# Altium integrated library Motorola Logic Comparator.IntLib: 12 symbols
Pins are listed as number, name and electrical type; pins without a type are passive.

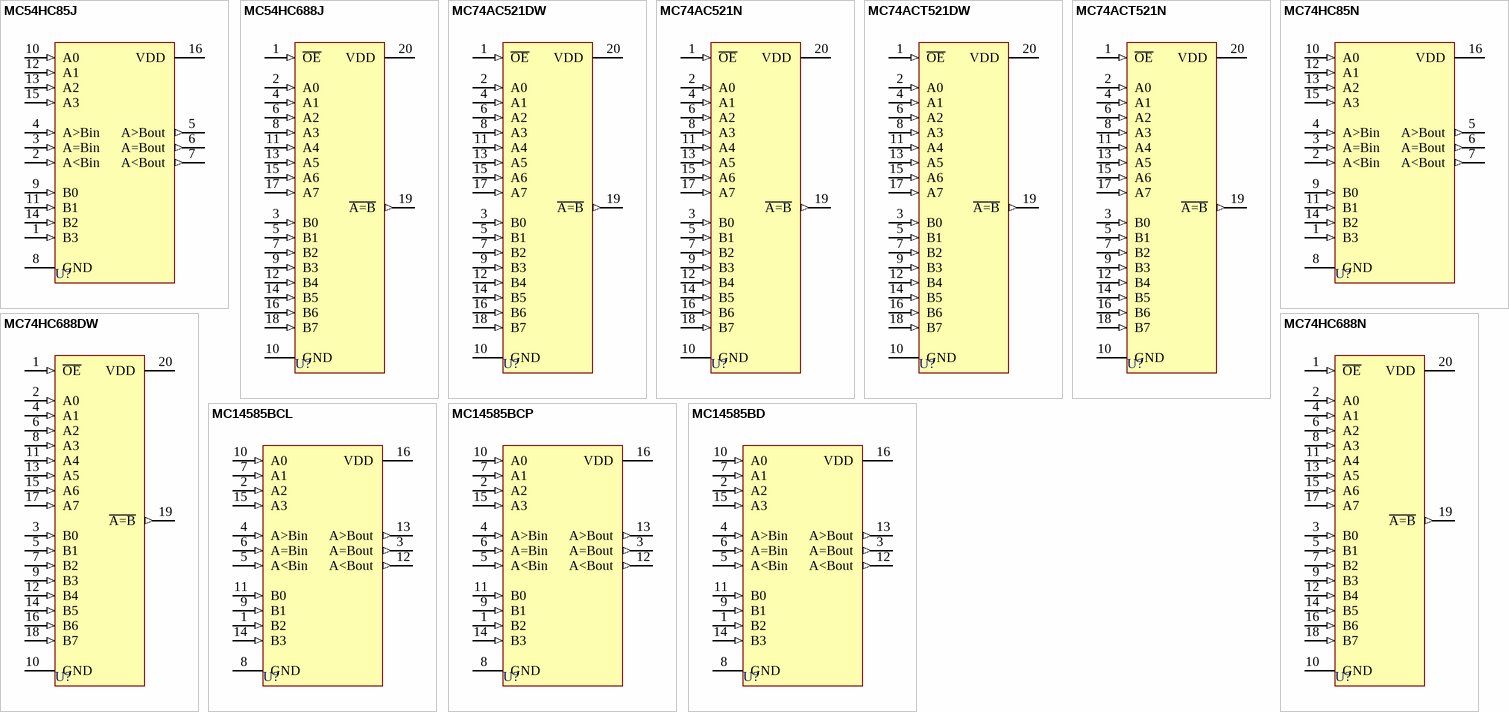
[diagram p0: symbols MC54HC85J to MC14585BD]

## MC54HC85J
designator U?
4-Bit Magnitude Comparator
footprint 620-09 (DIP; 16 Leads; Row Spacing 7.62 mm; Pitch 2.54 mm)
3D model 620-09 (DIP; 16 Leads; Row Spacing 7.62 mm; Pitch 2.54 mm)
signal-integrity model MC54HC85J
pins: 1 B3 (in), 2 A<Bin (in), 3 A=Bin (in), 4 A>Bin (in), 5 A>Bout (out), 6 A=Bout (out), 7 A<Bout (out), 8 GND (power), 9 B0 (in), 10 A0 (in), 11 B1 (in), 12 A1 (in), 13 A2 (in), 14 B2 (in), 15 A3 (in), 16 VDD (power)

## MC54HC688J
designator U?
8-Bit Equality Comparator
footprint 732-03 (DIP; 20 Leads; Row Spacing 7.62 mm; Pitch 2.54 mm)
3D model 732-03 (DIP; 20 Leads; Row Spacing 7.62 mm; Pitch 2.54 mm)
signal-integrity model MC54HC688J
pins: 1 ~{OE} (in), 2 A0 (in), 3 B0 (in), 4 A1 (in), 5 B1 (in), 6 A2 (in), 7 B2 (in), 8 A3 (in), 9 B3 (in), 10 GND (power), 11 A4 (in), 12 B4 (in), 13 A5 (in), 14 B5 (in), 15 A6 (in), 16 B6 (in), 17 A7 (in), 18 B7 (in), 19 ~{A=B} (out), 20 VDD (power)

## MC74AC521DW
designator U?
8-Bit Identity Comparator
footprint 751D-03_N (SOIC, 20-Leads, Body 12.8x7.5mm, Pitch 1.27mm, IPC Medium Density)
footprint 751D-03_L (SOIC, 20-Leads, Body 12.8x7.5mm, Pitch 1.27mm, IPC High Density)
footprint 751D-03_M (SOIC, 20-Leads, Body 12.8x7.5mm, Pitch 1.27mm, IPC Low Density)
3D model 751D-03 (20-Pin Small Outline Integrated Circuit 1.27 mm Pitch)
signal-integrity model MC74AC521DW
pins: 1 ~{OE} (in), 2 A0 (in), 3 B0 (in), 4 A1 (in), 5 B1 (in), 6 A2 (in), 7 B2 (in), 8 A3 (in), 9 B3 (in), 10 GND (power), 11 A4 (in), 12 B4 (in), 13 A5 (in), 14 B5 (in), 15 A6 (in), 16 B6 (in), 17 A7 (in), 18 B7 (in), 19 ~{A=B} (out), 20 VDD (power)

## MC74AC521N
designator U?
8-Bit Identity Comparator
footprint 738-03 (DIP; 20 Leads; Row Spacing 7.62 mm; Pitch 2.54 mm)
3D model 738-03 (DIP; 20 Leads; Row Spacing 7.62 mm; Pitch 2.54 mm)
signal-integrity model MC74AC521N
pins: 1 ~{OE} (in), 2 A0 (in), 3 B0 (in), 4 A1 (in), 5 B1 (in), 6 A2 (in), 7 B2 (in), 8 A3 (in), 9 B3 (in), 10 GND (power), 11 A4 (in), 12 B4 (in), 13 A5 (in), 14 B5 (in), 15 A6 (in), 16 B6 (in), 17 A7 (in), 18 B7 (in), 19 ~{A=B} (out), 20 VDD (power)

## MC74ACT521DW
designator U?
8-Bit Identity Comparator
footprint 751D-03_N (SOIC, 20-Leads, Body 12.8x7.5mm, Pitch 1.27mm, IPC Medium Density)
footprint 751D-03_L (SOIC, 20-Leads, Body 12.8x7.5mm, Pitch 1.27mm, IPC High Density)
footprint 751D-03_M (SOIC, 20-Leads, Body 12.8x7.5mm, Pitch 1.27mm, IPC Low Density)
3D model 751D-03 (20-Pin Small Outline Integrated Circuit 1.27 mm Pitch)
signal-integrity model MC74ACT521DW
pins: 1 ~{OE} (in), 2 A0 (in), 3 B0 (in), 4 A1 (in), 5 B1 (in), 6 A2 (in), 7 B2 (in), 8 A3 (in), 9 B3 (in), 10 GND (power), 11 A4 (in), 12 B4 (in), 13 A5 (in), 14 B5 (in), 15 A6 (in), 16 B6 (in), 17 A7 (in), 18 B7 (in), 19 ~{A=B} (out), 20 VDD (power)

## MC74ACT521N
designator U?
8-Bit Identity Comparator
footprint 738-03 (DIP; 20 Leads; Row Spacing 7.62 mm; Pitch 2.54 mm)
3D model 738-03 (DIP; 20 Leads; Row Spacing 7.62 mm; Pitch 2.54 mm)
signal-integrity model MC74ACT521N
pins: 1 ~{OE} (in), 2 A0 (in), 3 B0 (in), 4 A1 (in), 5 B1 (in), 6 A2 (in), 7 B2 (in), 8 A3 (in), 9 B3 (in), 10 GND (power), 11 A4 (in), 12 B4 (in), 13 A5 (in), 14 B5 (in), 15 A6 (in), 16 B6 (in), 17 A7 (in), 18 B7 (in), 19 ~{A=B} (out), 20 VDD (power)

## MC74HC85N
designator U?
4-Bit Magnitude Comparator
footprint 648-06 (DIP; 16 Leads; Row Spacing 7.62 mm; Pitch 2.54 mm)
3D model 648-06 (DIP; 16 Leads; Row Spacing 7.62 mm; Pitch 2.54 mm)
signal-integrity model MC74HC85N
pins: 1 B3 (in), 2 A<Bin (in), 3 A=Bin (in), 4 A>Bin (in), 5 A>Bout (out), 6 A=Bout (out), 7 A<Bout (out), 8 GND (power), 9 B0 (in), 10 A0 (in), 11 B1 (in), 12 A1 (in), 13 A2 (in), 14 B2 (in), 15 A3 (in), 16 VDD (power)

## MC74HC688DW
designator U?
8-Bit Equality Comparator
footprint 751D-03_N (SOIC, 20-Leads, Body 12.8x7.5mm, Pitch 1.27mm, IPC Medium Density)
footprint 751D-03_L (SOIC, 20-Leads, Body 12.8x7.5mm, Pitch 1.27mm, IPC High Density)
footprint 751D-03_M (SOIC, 20-Leads, Body 12.8x7.5mm, Pitch 1.27mm, IPC Low Density)
3D model 751D-03 (20-Pin Small Outline Integrated Circuit 1.27 mm Pitch)
signal-integrity model MC74HC688DW
pins: 1 ~{OE} (in), 2 A0 (in), 3 B0 (in), 4 A1 (in), 5 B1 (in), 6 A2 (in), 7 B2 (in), 8 A3 (in), 9 B3 (in), 10 GND (power), 11 A4 (in), 12 B4 (in), 13 A5 (in), 14 B5 (in), 15 A6 (in), 16 B6 (in), 17 A7 (in), 18 B7 (in), 19 ~{A=B} (out), 20 VDD (power)

## MC74HC688N
designator U?
8-Bit Equality Comparator
footprint 738-03 (DIP; 20 Leads; Row Spacing 7.62 mm; Pitch 2.54 mm)
3D model 738-03 (DIP; 20 Leads; Row Spacing 7.62 mm; Pitch 2.54 mm)
signal-integrity model MC74HC688N
pins: 1 ~{OE} (in), 2 A0 (in), 3 B0 (in), 4 A1 (in), 5 B1 (in), 6 A2 (in), 7 B2 (in), 8 A3 (in), 9 B3 (in), 10 GND (power), 11 A4 (in), 12 B4 (in), 13 A5 (in), 14 B5 (in), 15 A6 (in), 16 B6 (in), 17 A7 (in), 18 B7 (in), 19 ~{A=B} (out), 20 VDD (power)

## MC14585BCL
designator U?
4-Bit Magnitude Comparator
footprint 620-09 (DIP; 16 Leads; Row Spacing 7.62 mm; Pitch 2.54 mm)
3D model 620-09 (DIP; 16 Leads; Row Spacing 7.62 mm; Pitch 2.54 mm)
pins: 1 B2 (in), 2 A2 (in), 3 A=Bout (out), 4 A>Bin (in), 5 A<Bin (in), 6 A=Bin (in), 7 A1 (in), 8 GND (power), 9 B1 (in), 10 A0 (in), 11 B0 (in), 12 A<Bout (out), 13 A>Bout (out), 14 B3 (in), 15 A3 (in), 16 VDD (power)

## MC14585BCP
designator U?
4-Bit Magnitude Comparator
footprint 648-08 (DIP; 16 Leads; Row Spacing 7.62 mm; Pitch 2.54 mm)
3D model 620-09 (DIP; 16 Leads; Row Spacing 7.62 mm; Pitch 2.54 mm)
pins: 1 B2 (in), 2 A2 (in), 3 A=Bout (out), 4 A>Bin (in), 5 A<Bin (in), 6 A=Bin (in), 7 A1 (in), 8 GND (power), 9 B1 (in), 10 A0 (in), 11 B0 (in), 12 A<Bout (out), 13 A>Bout (out), 14 B3 (in), 15 A3 (in), 16 VDD (power)

## MC14585BD
designator U?
4-Bit Magnitude Comparator
footprint 751B-03_N (SOIC, 16-Leads, Body 9.9x3.9mm, Pitch 1.27mm, IPC Medium Density)
footprint 751B-03_L (SOIC, 16-Leads, Body 9.9x3.9mm, Pitch 1.27mm, IPC High Density)
footprint 751B-03_M (SOIC, 16-Leads, Body 9.9x3.9mm, Pitch 1.27mm, IPC Low Density)
3D model 751B-03 (16-Pin Small Outline Integrated Circuit 1.27 mm Pitch)
pins: 1 B2 (in), 2 A2 (in), 3 A=Bout (out), 4 A>Bin (in), 5 A<Bin (in), 6 A=Bin (in), 7 A1 (in), 8 GND (power), 9 B1 (in), 10 A0 (in), 11 B0 (in), 12 A<Bout (out), 13 A>Bout (out), 14 B3 (in), 15 A3 (in), 16 VDD (power)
